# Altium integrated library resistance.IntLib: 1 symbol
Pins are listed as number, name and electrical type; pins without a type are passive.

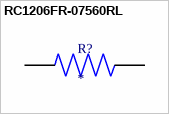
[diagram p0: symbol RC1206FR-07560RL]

## RC1206FR-07560RL
designator R?
560 Ohms Â±1% 0.25W, 1/4W Chip Resistor 1206 (3216 Metric) Moisture Resistant Thick Film; MF: Yageo; MP: RC1206FR-07560RL
footprint RESC3116X65N
pins: 1, 2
